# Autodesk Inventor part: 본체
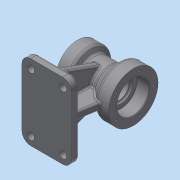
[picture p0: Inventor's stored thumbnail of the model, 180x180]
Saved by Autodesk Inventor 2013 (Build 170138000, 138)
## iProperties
Created: 2015-08
Part Number: 본체
Material: 일반
Document SubType Name: Modeling
Designer: Administrator
Density: 1 g/cm^3
Author: Administrator
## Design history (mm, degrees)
sketch "스케치1"
  geometry: L1 (-45, 0)-(-45, 35); L2 (-45, 35)-(-25, 35); L3 (-25, 35)-(-19.804, 26); L4 (-19.804, 26)-(8.315, 26); L5 (8.315, 26)-(25, 40); L6 (25, 40)-(45, 40); L7 (45, 40)-(45, 0); L8 (45, 0)-(-45, 0); 1 further point
  constraints: 16 end point, 4 parallel, 2 midpoint, 1 perpendicular, 1 vertical
  dimensions: "d0" = 90 distance of L7.end L1.start; "d2" = 35 distance of L1.start L1.end; "d3" = 40 distance of L6.end L7.end; "d4" = 20 distance of L1.end L2.end; "d5" = 20 distance of L5.end L6.end; "d6" = 40 deg angle of L5 L4; "d7" = 60 deg angle of L3 L4; "d8" = 26 distance between parallel lines of L8 L4
revolve "회전1" sketch "스케치1" stored, may be unused: angle "d9" = 90 deg
sketch "스케치2"
  geometry: L1 (-45, -78)-(35, -78); L2 (35, -78)-(35, -90); L3 (35, -90)-(-45, -90); L4 (-45, -90)-(-45, -78); L5 (-25, -35)-(-45, -35) reference; L6 (-45, -35)-(-45, 35) reference; L7 (-45, 35)-(-25, 35) reference; L8 (-25, 35)-(-19.804, 26) reference; L9 (-19.804, 26)-(8.315, 26) reference; L10 (8.315, 26)-(25, 40) reference; L11 (25, 40)-(45, 40) reference; L12 (45, 40)-(45, -40) reference; L13 (45, -40)-(25, -40) reference; L14 (25, -40)-(8.315, -26) reference; L15 (8.315, -26)-(-19.804, -26) reference; L16 (-19.804, -26)-(-25, -35) reference; 1 further point
  constraints: 8 end point, 2 parallel, 1 collinear, 1 horizontal, 1 perpendicular
  dimensions: "d10" = 80 distance of L2.end L3.end; "d13" = 90 distance from line of point (0, 0) L3; "d14" = 12 distance of L3.end L1.start
extrude "돌출1" join sketch "스케치2" stored distance "d15" = 122; taper "d16" = 0 deg
fillet "모깎기1" dims "d17" = 14
sketch "스케치3"
  geometry: L1 (-90, -61)-(-90, 61) reference; L2 (-90, 61)-(-78, 61) reference; L3 (-78, 61)-(-78, -61) reference; L4 (-78, -61)-(-90, -61) reference; L5 (-78, 51)-(-6.815, 25.091); L6 (-78, -51)-(-6.815, -25.091); L7 (-90, -61)-(-90, 61) reference; L8 (-90, 61)-(-78, 61) reference; L9 (-78, 61)-(-78, -61) reference; L10 (-78, -61)-(-90, -61) reference; C1 r 26 at (0, 0) reference; A1 r 26 centre (0, 0) between (-6.815, 25.091) and (-6.815, -25.091) reference; 1 further point
  constraints: 4 end point, 2 point on circle, 2 point on line
  dimensions: "d18" = 10 distance from line of L4 L6.start; "d19" = 10 distance from line of L2 L5.start; "d20" = 70 deg angle of L3 L6; "d21" = 70 deg angle of L3 L5
extrude "돌출2" join sketch "스케치3" distance "d22" = 12; taper "d23" = 0 deg
sketch "스케치4"
  geometry: L1 (-25, -35)-(-45, -35) reference; L2 (-45, -35)-(-45, 35) reference; L3 (-45, 35)-(-25, 35) reference; L4 (-25, 35)-(-19.804, 26) reference; L5 (-19.804, 26)-(8.315, 26) reference; L6 (8.315, 26)-(25, 40) reference; L7 (25, 40)-(45, 40) reference; L8 (45, 40)-(45, -40) reference; L9 (45, -40)-(25, -40) reference; L10 (25, -40)-(8.315, -26) reference; L11 (8.315, -26)-(0, -26) reference; L12 (-12, -78)-(-12, -26) reference; L13 (0, -78)-(35, -78) reference; L14 (35, -78)-(35, -90) reference; L15 (35, -90)-(-45, -90) reference; L16 (-45, -90)-(-45, -78) reference; L17 (-45, -78)-(-12, -78) reference; L18 (0, -26)-(0, -78) reference; L19 (-12, -26)-(-19.804, -26) reference; L20 (-19.804, -26)-(-25, -35) reference; L21 (-35, -78)-(-35, -35); L22 (25, -78)-(31.7, -40); 1 further point
  constraints: 4 end point, 3 point on line, 1 midpoint, 1 perpendicular
  dimensions: "d24" = 10 distance between parallel lines of L21 L16; "d25" = 10 distance from line of L14 L22.start; "d26" = 80 deg angle of L13 L22
  node "절단 모서리 투영4"
feature "리브1" dims "d27" = 1, "d28" = 12, "d29" = 0, "d30" = 0, "d31" = 1, "d32" = 1
feature "리브2" dims "d33" = 1, "d34" = 12, "d35" = 0, "d36" = 0, "d37" = 1, "d38" = 1
sketch "스케치6"
  geometry: A1 r 14 centre (52, -14) between (66, -14) and (52, 0) reference; A2 r 14 centre (0, -14) between (0, 0) and (-14, -14) reference; A3 r 14 centre (0, -108) between (-14, -108) and (0, -122) reference; A4 r 14 centre (52, -108) between (52, -122) and (66, -108) reference; 5 further points
  constraints: 4 coincident
hole "구멍1" sketch "스케치6" at (0, -108), (52, -108), (52, -14), (0, -14) diameter "d40" = 12; stored, may be unused: countersink angle "d44" = 90 deg, drill point angle "d46" = 118 deg; dims "d41" = 6, "d42" = 4, "d43" = 2, "d45" = 8
hole "구멍2" diameter "d49" = 38; stored, may be unused: countersink angle "d53" = 90 deg, drill point angle "d55" = 0 deg; dims "d47" = 10, "d48" = 10, "d50" = 6, "d51" = 52, "d52" = 20, "d54" = 23
hole "구멍3" diameter "d58" = 32; stored, may be unused: countersink angle "d62" = 90 deg, drill point angle "d64" = 0 deg; dims "d56" = 10, "d57" = 10, "d59" = 6, "d60" = 40, "d61" = 17, "d63" = 23
fillet "모깎기3" dims "d65" = 0.3, "d66" = 3
chamfer "모따기1" distance "d67" = 1; stored, may be unused: second distance "d68" = 2, angle "d69" = 45 deg
sketch "스케치9"
  geometry: C1 r 40 at (0, 0) reference; 1 further point
  constraints: 1 vertical alignment
  dimensions: "d70" = 33 distance of point (0, 33) C1.centre
hole "구멍4" sketch "스케치9" at (0, 33) diameter "d71" = 3.242; stored, may be unused: countersink angle "d75" = 90 deg, drill point angle "d77" = 118 deg; dims "d72" = 10, "d73" = 40, "d74" = 17, "d76" = 13
sketch "스케치10"
  geometry: C1 r 35 at (0, 0) reference; 1 further point
  constraints: 1 vertical alignment
  dimensions: "d81" = 27 distance of point (0, 27) C1.centre
hole "구멍5" sketch "스케치10" at (0, 27) diameter "d82" = 3.242; stored, may be unused: countersink angle "d86" = 90 deg, drill point angle "d88" = 118 deg; dims "d83" = 10, "d84" = 40, "d85" = 17, "d87" = 13
sketch "스케치11"
  geometry: L1 (-30, -54)-(-30, -60); L2 (-18, -54)-(-18, -60); L3 (-61, -78)-(-47, -78) reference; A1 r 26 centre (0, 0) between (-25.091, -6.815) and (-6, -25.298) reference; A2 r 6 centre (-24, -54) between (-18, -54) and (-30, -54); A3 r 6 centre (-24, -60) between (-30, -60) and (-18, -60)
  constraints: 4 end point, 4 point on circle, 4 tangent, 2 centre point, 1 equal radius, 1 vertical alignment
  dimensions: "d92" = 12 diameter of A2; "d93" = 18 dimension on A3 A2; "d94" = 24 horizontal distance of A1.centre A3.centre; "d95" = 18 distance from line of A3.centre L3
extrude "돌출3" cut sketch "스케치11" stored distance "d96" = 12; taper "d97" = 0 deg
fillet "모깎기4" dims "d98" = 3
fillet "모깎기5" dims "d99" = 3
fillet "모깎기6" dims "d100" = 3
fillet "모깎기7" dims "d101" = 3
fillet "모깎기8" dims "d102" = 5
fillet "모깎기9" dims "d103" = 3
sketch "스케치12"
  geometry: L1 (57, 56.972)-(57, 50.01) reference; L2 (57.3, 49.702)-(76, 49.702) reference; L3 (77, 48.675)-(77, 35.453) reference; L4 (77, 35.453)-(65.196, 35.453) reference; L5 (60.293, 32.952)-(58.82, 32.952) reference; L6 (38.496, 47.432)-(35, 47.432) reference; L7 (35, 47.432)-(35, 0) reference; L8 (35, 0)-(54.483, 0) reference; L9 (60.293, 32.952)-(54.483, 0) reference; L10 (4, 60.168)-(54, 60.168) reference; L11 (4, 56.236)-(4, 60.168) reference; L12 (-12, 55.921)-(3.7, 55.921) reference; L13 (-13, 40.518)-(-13, 54.875) reference; L14 (-4.863, 40.518)-(-13, 40.518) reference; L15 (0, 0)-(0, 38.081) reference; L16 (0, 0)-(17, 0) reference; L17 (17, 0)-(17, 47.432) reference; L18 (17, 47.432)-(15.083, 47.432) reference; L19 (4.113, 38.081)-(0, 38.081) reference; L20 (59.759, -3)-(64, -3) reference; L21 (67, -6)-(67, -15) reference; L22 (67, -15)-(-13, -15) reference; L23 (-13, -15)-(-13, -6) reference; L24 (-10, -3)-(-5.196, -3) reference; L25 (54, 89.832)-(4, 89.832) reference; L26 (4, 89.832)-(4, 93.764) reference; L27 (3.7, 94.079)-(-12, 94.079) reference; L28 (-13, 95.125)-(-13, 109.482) reference; L29 (-13, 109.482)-(4.113, 109.482) reference; L30 (15.083, 100.298)-(38.496, 100.298) reference; L31 (58.82, 114.547)-(77, 114.547) reference; L32 (77, 114.547)-(77, 101.325) reference; L33 (76, 100.298)-(57.3, 100.298) reference; L34 (57, 99.99)-(57, 93.028) reference; L35 (-3, 37.119)-(-3, 0) reference; A1 r 3 centre (64, -6) between (67, -6) and (64, -3) reference; A2 r 3 centre (-10, -6) between (-10, -3) and (-13, -6) reference; 10 further points
  constraints: 27 other
  dimensions: "d104" = 24 distance from line of point (13, 21) L24; "d105" = 16 distance from line of point (13, 21) L35
feature "엠보싱1" sketch "스케치12" dims "d106" = 0.5, "d107" = 0
node "솔리드1"
pattern_circular "원형 패턴1" dims angle "d79" = 360 deg
pattern_circular "원형 패턴2" dims angle "d90" = 360 deg
mirror "대칭1"
node "절단 모서리 투영1"
node "절단 모서리 투영2"
node "절단 모서리 투영3"
node "절단 모서리 투영6"
